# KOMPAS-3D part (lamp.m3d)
File: created 18.09.2016 11:39:13, last saved 18.09.2016 14:08:06.
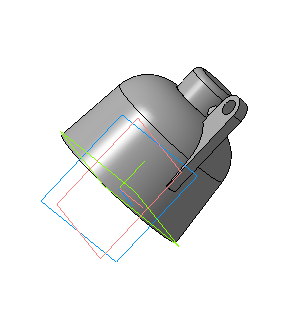
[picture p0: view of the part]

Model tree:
1. Эскиз:1
2. Операция вращения:1
     Угол 1 = 360
3. Эскиз:2
4. Операция выдавливания:1
     Расстояние 1 = 5
5. Эскиз:3
6. Вырезать элемент выдавливания:1
     Расстояние 2 = 15; Расстояние 1 = 10
7. Скругление:2
     Радиус = 3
